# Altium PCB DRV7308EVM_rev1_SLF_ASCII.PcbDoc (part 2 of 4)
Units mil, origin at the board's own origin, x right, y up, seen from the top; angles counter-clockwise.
Board outline 6187 x 6000 mil, 4 copper layers (Top Layer, Ground, Power, Bottom Layer), stack 61.2 mil thick; 306 components, 128 nets, 676 pads, 1026 vias.
Unrouted connection lines stored in the file: 208.
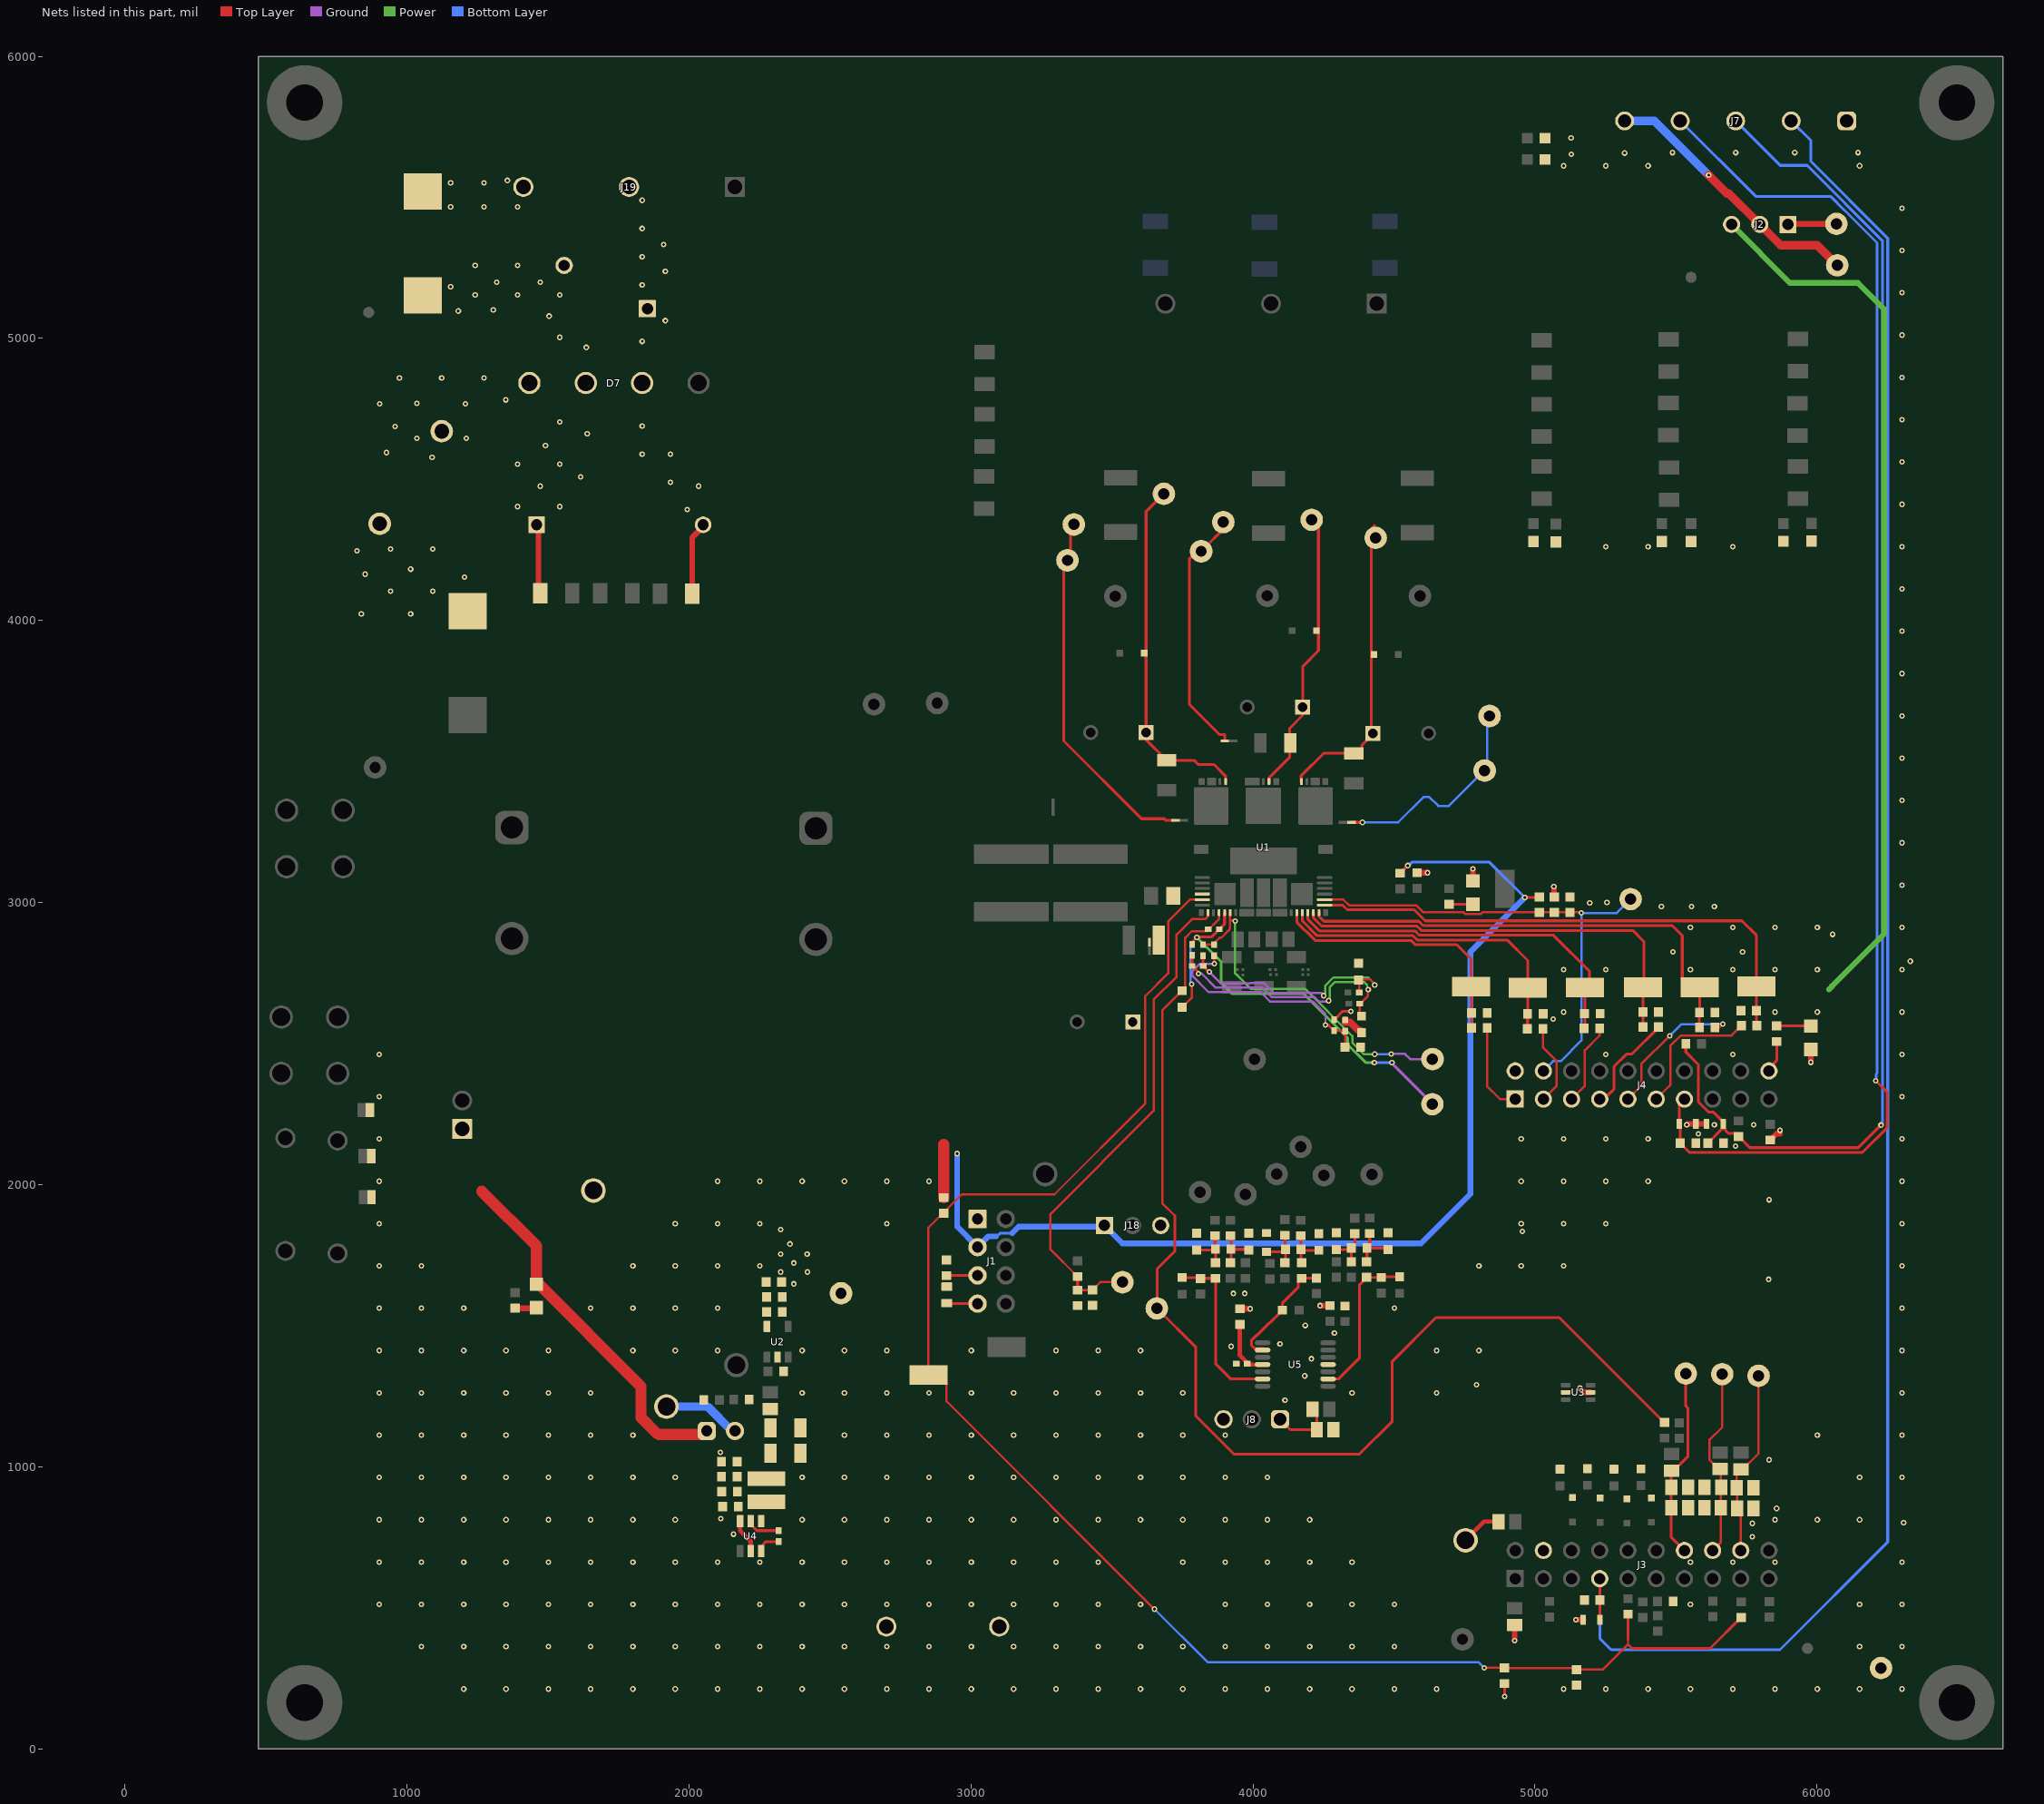
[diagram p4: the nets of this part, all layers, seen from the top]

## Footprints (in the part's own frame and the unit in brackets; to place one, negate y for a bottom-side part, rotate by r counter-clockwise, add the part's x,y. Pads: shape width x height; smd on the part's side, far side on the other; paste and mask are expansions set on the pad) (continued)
PW0014A_N [mm] "TSOP, 14-Leads, Body 5x4.4mm, Pitch 0.65mm, IPC Medium Density"
  oval 1.4x0.45 smd: 1(-2.95,1.95) 2(-2.95,1.3) 3(-2.95,0.65) 4(-2.95,0) 5(-2.95,-0.65) 6(-2.95,-1.3) 7(-2.95,-1.95) 8(2.95,-1.95) 9(2.95,-1.3) 10(2.95,-0.65) 11(2.95,0) 12(2.95,0.65) 13(2.95,1.3) 14(2.95,1.95)
  silkscreen extent -3.4,-2.55 1.85,2.55
REN0065A-MFG [mm]
  rrect22% 0.6x0.446 smd paste+0 mask+0: 1(-5.9,5.598) 23(-5.9,-5.598)
  rrect40% 0.6x0.25 smd paste+0 mask+0: 2(-5.9,5) 3(-5.9,4.5) 4(-5.9,4) 5(-5.9,3.5) 6(-5.9,3) 7(-5.9,2.5) 17(-5.9,-2.5) 18(-5.9,-3) 19(-5.9,-3.5) 20(-5.9,-4) 21(-5.9,-4.5) 22(-5.9,-5) 40(5.9,-3.916) 41(5.9,-3.416) 43(5.9,-0.5) 44(5.9,0) 48(5.9,3.416) 49(5.9,3.916)
  rrect40% 0.6x0.25 smd paste-1000 mask+0: 8(-5.9,2) 9(-5.9,1.5) 10(-5.9,1) 11(-5.9,0.5) 12(-5.9,0) 13(-5.9,-0.5) 14(-5.9,-1) 15(-5.9,-1.5) 16(-5.9,-2) 38(5.9,-4.916) 39(5.9,-4.416) 45(5.9,0.5) 46(5.9,1) 47(5.9,1.5) 50(5.9,4.416) 51(5.9,4.916)
  rrect40% 0.25x1.375 smd paste-1000 mask+0: 24(-5.225,-5.513) 25(-4.725,-5.513) 26(-4.225,-5.513) 27(-3.725,-5.513) 28(-3.225,-5.513) 29(-2.725,-5.513) 60(-2.725,5.513) 61(-3.225,5.513) 62(-3.725,5.513) 63(-4.225,5.513) 64(-4.725,5.513) 65(-5.225,5.513)
  rrect40% 0.25x0.45 smd paste+0 mask+0: 30(-0.45,-5.975) 31(0.05,-5.975) 58(0.05,5.975) 59(-0.45,5.975)
  rrect22% 0.5x0.455 smd paste+0 mask+0: 32(2.65,-5.973) 36(4.9,-5.973) 53(4.9,5.973) 57(2.65,5.973)
  rrect40% 0.25x0.455 smd paste+0 mask+0: 33(3.275,-5.973) 34(3.775,-5.973) 35(4.275,-5.973) 54(4.275,5.973) 55(3.775,5.973) 56(3.275,5.973)
  rrect18% 0.6x0.55 smd paste+0 mask+0: 37(5.9,-5.566) 42(5.9,-1.15) 52(5.9,5.566)
  rrect5% 1.975x1.94 smd paste-1000 mask+0: 66(-4.221,3.465) 70(-4.221,-3.465)
  rrect8% 2.601x1.25 smd paste-1000 mask+0: 67(-4.099,1.475) 69(-4.099,-1.475)
  rrect8% 2.601x1.2 smd paste-1000 mask+0: 68(-4.099,0)
  rrect4% 2.41x6 smd paste-1000 mask+0: 71(-1.233,0)
  rrect3% 3.278x3.175 smd paste-1000 mask+0: 72(3.711,0)
  rrect29% 0.7x1.35 smd paste-1000 mask+0: ""(-5.9,-1.5) ""(-5.9,0) ""(-5.9,1.5) ""(5.9,1)
  rrect24% 0.85x1.301 smd paste-1000 mask+0: ""(-0.2,5.6) ""(-0.2,-5.6)
  rrect6% 3.378x3.097 smd paste-1000 mask+0: ""(3.711,-4.702) ""(3.711,4.702)
  rrect29% 0.7x0.85 smd paste-1000 mask+0: ""(5.9,-4.666) ""(5.9,4.666)
  silkscreen extent -6.87,-6.43 6.43,6.43
Samtec_SSQ-110-03-x-D [mm] "Receptacle, 2.54mm, 10x2, TH"
  rect 1.55x1.55 hole 1.02: 1(-11.43,1.27)
  round 1.55 hole 1.02: 2(-11.43,-1.27) 3(-8.89,1.27) 4(-8.89,-1.27) 5(-6.35,1.27) 6(-6.35,-1.27) 7(-3.81,1.27) 8(-3.81,-1.27) 9(-1.27,1.27) 10(-1.27,-1.27) 11(1.27,1.27) 12(1.27,-1.27) 13(3.81,1.27) 14(3.81,-1.27) 15(6.35,1.27) 16(6.35,-1.27) 17(8.89,1.27) 18(8.89,-1.27) 19(11.43,1.27) 20(11.43,-1.27)
  silkscreen extent -12.95,-2.48 12.95,3
SNT-100-BK-G [mil] "Samtec STEP model"
  round 1 on Mech3: 0(0,0)
SOD-323 [mm] "NXP recommended land pattern"
  rect 0.6x0.6 smd paste-0.05: 1(-1.1,0) 2(1.1,0)
  silkscreen extent -2.06,-0.86 1.53,0.86
Testpoint_Keystone_Miniature [mil] "Miniature SMT test point"
  rect 135x70 smd: 1(0,0)
  silkscreen extent -78,-46 78,45
Thermistor_CL-40 [mil] "GE"
  round 80 hole 52: 1(-164,110) 2(164,-110)
  silkscreen extent -402,-118 402,118
TI_Stacked_Overlay_Small [mil]
TNPW0603 [mm] "Vishay"
  rect 0.5x0.9 smd: 1(-0.75,0) 2(0.75,0)
  silkscreen extent -0.2,-0.6 0.2,0.6
TSW-102-07-G-S [mm] "Samtec 100mil, 1x2, 230 mil above insulator"
  rrect50% 1.65x1.65 hole 1.016: 1(-1.27,0)
  round 1.65 hole 1.016: 2(1.27,0)
  silkscreen extent -3.17,-1.27 2.54,1.27
TSW-104-07-G-D [mm] "Samtec 100mil, 2x4, 230 mil above insulator"
  rrect6% 1.65x1.65 hole 1.016: 1(-3.81,-1.27)
  round 1.65 hole 1.016: 2(-3.81,1.27) 3(-1.27,-1.27) 4(-1.27,1.27) 5(1.27,-1.27) 6(1.27,1.27) 7(3.81,-1.27) 8(3.81,1.27)
  silkscreen extent -6.1,-2.54 5.08,2.54
WCAP-CSGP_0603_L1.6W0.8H0.8_Reflow [mm] "Ceramic Capacitors, body 1.6x0.8mm"
  rect 0.8x0.8 smd: 1(-0.75,0) 2(0.75,0)
WCAP-CSGP_0603_L1.6W0.8H0.8_Wave [mm] "Ceramic Capacitors, 0603, body 1.6x0.8mm"
  rect 0.7x0.8 smd: 1(-0.85,0) 2(0.85,0)
WE-MAIA_3015 [mm] "SMD, 2-Leads, Body 3x3mm"
  rect 1.3x3.4 smd: 1(-1.05,0) 2(1.05,0)
  silkscreen extent -0.1,-1.6 0.1,1.6
WEEE_Minimum [mil] "WEEElie bin"
  silkscreen extent 22,-71 54,74
WURTH_61300311121 [mm] "Header, 2.54mm, 3x1, TH"
  rrect50% 1.65x1.65 hole 1.15: 1(-2.54,0)
  round 1.65 hole 1.15: 2(0,0) 3(2.54,0)

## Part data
C1 C3 C5: library part CMP-0008509-2, "CAP, CERM, 1 uF, 25 V, +/- 10%, X7R, 1206"
C2: library part CMP-0006343-2, "CAP, CERM, 0.1 uF, 10 V, +/- 10%, X7R, 0402"
C4 C47 C48 C49: library part CMP-0007796-2, "CAP, CERM, 470 pF, 50 V, +/- 10%, X7R, 0805"
C6 C8: library part CMP-0097628-1, "2225 0.1 uF 1 kV ±10 % Tolerance X7R SMT Multilayer Ceramic Chip Capacitor"
C7 C35 C52: library part CMP-0006837-2, "CAP, CERM, 0.1 uF, 50 V, +/- 10%, X7R, 0603"
C9: library part CMP-0007567-1, "CAP, CERM, 0.1 uF, 25 V, +/- 10%, X7R, 0805"
C10: library part CMP-0009224-2, "CAP, CERM, 22 uF, 25 V, +/- 10%, X7R, 1210"
C11: library part CMP-0860561-1, "CAP, CERM, 0.01 µF, 25 V,+/- 10%, X7R, 0402"
C12 C16 C17 C24 C36 C37 C40 C41 C43 C44 C46 C50: library part CMP-0104643-1, "WCAP-CSGP Multilayer Ceramic Chip Capacitor, General Purpose, size 0603, X7R, 100pF, 10VDC"
C13 C14 C15 C34: library part CMP-0086483-1, "0.047µF ±10% 25V Ceramic Capacitor X7R 0603 (1608 Metric)"
C18 C19 C20 C21 C22 C23: library part CMP-0064933-2, "CAP, CERM, 1000 pF, 50 V,+/- 10%, X7R, 0603"
C25 C26 C27: library part CMP-0006826-2, "CAP, CERM, 1000 pF, 16 V, +/- 10%, X7R, 0603"
C28 C55: library part CMP-0007505-3, "CAP, CERM, 1 uF, 10 V, +/- 10%, X7R, AEC-Q200 Grade 1, 0603"
C29 C30 C31: library part CMP-0076705-1, "CAP, CERM, 1 µF, 25 V,+/- 10%, X7R, AEC-Q200 Grade 1, 0603"
C32 C54: library part CMP-0080740-1, "CAP, CERM, 10 µF, 25 V,+/- 10%, X7R, 1206"
C33: library part CMP-0007119-4, "CAP, CERM, 0.1 uF, 16 V, +/- 10%, X7R, 0603"
C38: library part CMP-0006263-2, "CAP, CERM, 2.2 uF, 10 V, +/- 10%, X5R, 0402"
C39 C42 C45: library part CMP-0006826-4, "CAP, CERM, 1000 pF, 16 V, +/- 10%, X7R, 0603"
C53: library part CMP-0006726-4, "CAP, CERM, 0.01 uF, 100 V, +/- 5%, X7R, 0603"
C56: library part CMP-0012410-1, "CAP, Film, 0.33 uF, 630 V, +/- 20%, TH"
C57 C58: library part CMP-0085509-1, "CAP, AL, 150 µF, 450 V, +/- 20%, 1.216 ohm, TH"
C59 C60 C61: library part CMP-0010527-1, "CAP, AL, 220 uF, 25 V, +/- 20%, 0.1 ohm, TH"
C62 C63 C64: library part CMP-0009436-1, "CAP, CERM, 1000 pF, 2000 V, +/- 10%, X7R, 1808"
C67: library part CMP-0010362-1, "CAP, AL, 1000 uF, 25 V, +/- 20%, TH"
D2: library part CMP-0002829-1, "LED, Red, SMD"
D3: library part CMP-0002888-1, "LED, Green, SMD"
D4: library part CMP-0002890-1, "LED, Orange, SMD"
D7: library part CMP-0029245-3, "Diode, Switching-Bridge, 600 V, 6 A, TH"
D9 D10 D11 D12: library part CMP-0084035-2, "Diode, Schottky, 7 V, 0.01 A, SOD-323"
D14 D15 D16: library part CMP-0005835-4, "Diode, Zener, 18 V, 200 mW, SOD-323"
F1 F2: library part CMP-0003468-2, "Fuse, 3 A, 250VAC/VDC, SMD"
FID1 FID2 FID3: library part CMP-0077181-1, "Fiducial mark.  There is nothing to buy or mount."
H9 H10 H11 H12: library part CMP-0003640-1, "Standoff, Hex,25mm Length, M3, Aluminum"
H13 H14 H15 H16: library part CMP-0003646-1, "MACHINE SCREW PAN PHILLIPS M3 5mm"
J1: library part CMP-0075408-2, "Header, 100mil, 4x2, Gold, TH"
J2 J18: library part CMP-0065026-1, "Header, 2.54mm, 3x1, Tin, TH"
J3 J4: library part CMP-0075613-1, "Receptacle, 2.54mm, 10x2, Gold, TH"
J5: library part CMP-0055418-2, "Banana Jack Insul Nylon Red, R/A, TH"
J6 J19: library part CMP-0055528-1, "Terminal Block, 9.52mm, 3x1, R/A, TH"
J7: library part CMP-0055532-1, "Terminal Block, 5mm, 5x1, R/A, TH"
J8: library part CMP-0054796-2, "Header, 2.54 mm, 3x1, Gold, TH"
J9: library part CMP-0075076-1, "Terminal Block, 2.54mm, 2x1, Brass, TH"
J10: library part CMP-0055417-2, "Banana Jack Insul Nylon Black, R/A, TH"
J17: library part CMP-0075405-3, "Header, 100mil, 2x1, Gold, TH"
L1: library part CMP-0064361-1, "Inductor, Shielded, Powdered Iron, 4.7 uH, 1.5 A, 0.162 ohm, AEC-Q200 Grade 1, SMD"
L2 L3 L4: library part CMP-0003168-1, "Ferrite Bead, 120 ohm @ 100 MHz, 3 A, 1812"
LOGO LOGO5 LOGO7: library part CMP-0074837-1, "IEC 61010-1 Hot Surface Warning"
Logo1: library part CMP-0074844-1
Logo2: library part CMP-0074838-1, "Texas Instrument Corporate Signature"
Logo3: library part CMP-0074847-1, "FCC_disclaimer"
Logo4: library part CMP-0074769-1
LOGO6 LOGO8: library part CMP-0074835-1, "IEC 61010-1 High Voltage Warning"
MH5 MH6 MH7 MH8: library part CMP-0078423-2, "PCB Mounting Hole"
NT1 NT2 NT14: library part CMP-0078142-1, "Single point connection between nets."
NT3 NT4 NT5 NT6 NT7 NT8 NT9 NT10 NT11 NT12 NT13: library part CMP-0078142-4, "Single point connection between nets."
R1: library part CMP-0022073-1, "RES, 162 k, 1%, 0.1 W, 0603"
R2 R48 R49 R50 R51 R54 R78 R79 R135 R137 R138 R139: library part CMP-0025874-4, "RES, 0, 5%, 0.1 W, AEC-Q200 Grade 0, 0603"
R3 R6 R37: library part CMP-0017262-1, "RES, 0.03, 1%, 0.5 W, 1206"
R4: library part CMP-0024951-1, "RES, 22.1 k, 0.5%, 0.1 W, 0603"
R5 R21: library part CMP-0020616-1, "RES, 0, 5%, 0.125 W, 0805"
R7 R13 R36: library part CMP-0020616-3, "RES, 0, 5%, 0.125 W, AEC-Q200 Grade 0, 0805"
R8 R45 R128: library part CMP-0026162-2, "RES, 20.0 k, 1%, 0.063 W, AEC-Q200 Grade 0, 0402"
R9 R11: library part CMP-0025964-3, "RES, 10.2, 1%, 0.063 W, AEC-Q200 Grade 0, 0402"
R10 R12 R129: library part CMP-0026676-1, "RES, 2.00 k, 1%, 0.1 W, AEC-Q200 Grade 0, 0402"
R14 R70 R71 R72: library part CMP-0082535-1, "RES, 330, 1%, 0.125 W, 0805"
R15 R17: library part CMP-0078582-1, "RES, 330, 0.1%, 0.1 W, AEC-Q200 Grade 0, 0603"
R16: library part CMP-0024300-2, "RES, 4.70 k, 0.1%, 0.1 W, 0603"
R18 R19 R20 R75 R76 R77 R120: library part CMP-0022736-4, "RES, 100, 1%, 0.1 W, 0603"
R22 R121 R122: library part CMP-0018205-2, "RES, 330 k, 1%, 0.25 W, 1206"
R29 R30 R31: library part CMP-0025686-1, "RES, 10.0 k, 0.1%, 0.1 W, AEC-Q200 Grade 1, 0603"
R34 R41 R117 R123 R124 R125 R126 R127: library part CMP-0025830-1, "RES, 5.1 k, 5%, 0.1 W, 0603"
R43: library part CMP-0025701-4, "RES, 10 k, 5%, 0.1 W, AEC-Q200 Grade 0, 0603"
R44: library part CMP-0095619-1, "RES Thick Film, 68kO, 1%, 0.1W, 100ppm/°C, 0603"
R46 R57 R58 R63 R64 R69 R118: library part CMP-0022447-4, "RES, 49.9 k, 1%, 0.1 W, AEC-Q200 Grade 0, 0603"
R47: library part CMP-0025697-4, "RES, 0, 5%, 0.1 W, AEC-Q200 Grade 0, 0603"
R52 R55 R59 R61 R65 R67: library part CMP-0022005-4, "RES, 10.2, 1%, 0.1 W, AEC-Q200 Grade 0, 0603"
R53 R56 R60 R62 R66 R68: library part CMP-0022458-4, "RES, 4.99 k, 1%, 0.1 W, AEC-Q200 Grade 0, 0603"
R73 R74: library part CMP-0021990-4, "RES, 100 k, 1%, 0.1 W, AEC-Q200 Grade 0, 0603"
R91 R92 R93 R94 R98 R110 R111 R112 R113 R116 R130 R134: library part CMP-0018207-2, "RES, 332 k, 1%, 0.25 W, 1206"
R99 R100 R101 R102 R103 R104 R105 R106: library part CMP-0023308-5, "RES, 8.20 k, 1%, 0.1 W, 0603"
R107 R108 R109: library part CMP-0021042-1, "RES, 20.0 k, 1%, 0.125 W, 0805"
R119: library part CMP-0022280-2, "RES, 2.67 k, 1%, 0.1 W, 0603"
RT1: library part CMP-0002561-2, "Thermistor NTC, 5 ohm, 25%, Disc, 220x770 mil"
RV1: library part CMP-0086467-2, "Var MOV 350VAC/460VDC 3500A 560V Radial Bulk"
SH-J1 SH-J2 SH-J3 SH-J4 SH-J5: library part CMP-0003623-3, "Shunt, 100mil, Gold plated, Black"
TP1 TP2 TP3: library part CMP-0055137-1, "Test Point, Miniature, Red, TH"
TP4 TP5 TP6 TP7 TP9 TP10 TP29 TP32 TP34 TP35 TP40 TP41: library part CMP-0055137-2, "Test Point, Miniature, Red, TH"
TP8 TP18 TP20 TP21 TP22 TP23 TP24 TP43 TP45: library part CMP-0055152-1, "Test Point, Miniature, SMT"
TP11 TP12 TP13: library part CMP-0075110-1, "1mm Uninsulated Shorting Plug, 10.16mm spacing, TH"
TP14 TP26 TP31 TP36 TP37 TP38 TP39 TP44 TP46 TP47 TP48 TP49 TP52 TP53 TP54 TP55 TP56 TP57: library part CMP-0055139-2, "Test Point, Miniature, White, TH"
TP16 TP17: library part CMP-0055138-1, "Test Point, Miniature, Black, TH"
TP19 TP30 TP33 TP42 TP50: library part CMP-0055146-2, "Test Point, Compact, Yellow, TH"
U1: library part CMP-0098388-1, "Three-Phase, 650-V Integrated GaN FET Motor Driver, VQFN65"
U2: library part CMP-0065093-2, "Low-Dropout Regulator, DBV0005A (SOT-23-5)"
U3: library part CMP-0043118-3, "4-Channel ESD Solution for High-Speed Differential Interface, DCK0006A (SOT-SC70-6)"
U4: library part CMP-0094075-1, "SIMPLE SWITCHER 4.5-V to 36-V, 2-A Buck Converter in SOT-23-6 Package"
U5: library part CMP-0082283-1, "4 channel, 10-MHz, Low-Noise, RRIO, CMOS Operational Amplifier for Cost-Sensitive Systems, PW0014A (TSSOP-14)"
ZZ1: library part CMP-0003616-3
ZZ2: library part CMP-0077236-1
ZZ3: library part CMP-0077237-1
ZZ4: library part CMP-0077238-1

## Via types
v1: diameter 20, hole 10, Top Layer to Bottom Layer, tented both sides, 933 vias
v2: diameter 19.68, hole 7.87, Top Layer to Bottom Layer, tented both sides, 57 vias
v3: diameter 39.37, hole 19.68, Top Layer to Bottom Layer, tented both sides, 24 vias
v4: diameter 20, hole 10, Top Layer to Bottom Layer, tented bottom, 12 vias

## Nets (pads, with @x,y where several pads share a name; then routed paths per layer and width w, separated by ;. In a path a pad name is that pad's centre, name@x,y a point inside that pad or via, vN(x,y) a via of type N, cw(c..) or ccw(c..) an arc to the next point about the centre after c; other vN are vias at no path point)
3V3: D2.1 D4.1 J2.3 J18.3 R8.2 R13.1 R29.2 R30.2 R31.2 R41.2 R47.2 R51.1 R54.2 R73.2 R117.1 R125.1 TP26.1 U3.5 | length 3762.8
  Top Layer w10: R8.2@4288,2584.69 4317.31,2614 v1(4347.27,2614) ; R117.1@4891.82,231 4891.82,186 v1(4892.82,185)
  Top Layer w20: R47.2@3953.26,1559.7 v1(3989.7,1559.7) ; v1(4237.82,1570.7) R73.2@4273.26,1570.7 ; R41.2@4582,3105.56 v1(4618.56,3105.56) ; D2.1@4780,3076.76 v1(4780,3119) ; v1(4927.82,383) R13.1@4927.82,439.07 ; v1(5066.9,3056.78) 5068,3055.69 R125.1@5068,3019.56 ; v1(5144.82,457) R31.2@5171.29,457 ; v1(5159.09,1278.38) 5173.37,1264.1 5196.66,1264.1 U3.5@5197.38,1263.38 ; v1(5538.18,2211.89) 5541.29,2215 R30.2@5608.29,2215 ; R51.1@5834.82,2158.44 5857.19,2180.81 5868.55,2180.81 v1(5868.55,2192.17) ; v1(5978.28,2433.42) D4.1@5978.28,2479.08
  Power w20: J2.3@5697,5404 5904,5197 6145.13,5197 6238,5104.13 6238,2889 6053,2704 6053,2702 6043,2692
  other v1: 2372,1648 2325,1690 2420,1690 2372,1722 2325,1754 2419,1754 2358,1789.53 2325,1840
+5V: R36.2 TP30.1 | length 144.8
  Top Layer w15: TP30.1@4753.82,739 4819.82,805 R36.2@4871.29,805
AMPIN+: R10.2 R45.1 TP37.1 U1.6 | length 1226.3
  Top Layer w8: R10.2@3824,2850.69 R45.1@3860,2850.69 ; R45.1@3863,2853.69 R45.1@3860,2850.69 ; U1.6@3918.96,2964.09 3918.96,2937 ; v1(3936.5,2934.5) 3934,2937 3918.96,2937 ; R45.1@3860,2850.69 3860,2853.7 3881.3,2875 3887.89,2875 3912.82,2899.92 3912.82,2901.12 3918.96,2907.26 3918.96,2937
  Ground w8: v1(4489.99,2463.16) 4539.17,2463.16 4557.32,2445.01 TP37.1@4636.51,2445.01
  Power w8: v1(3936.5,2934.5) 3936.5,2749.15 3991.65,2694 4184.84,2694 4352.46,2526.38 4352.46,2503.3 4393.76,2462 v1(4431.61,2462)
  Bottom Layer w8: v1(4431.61,2462) 4484.45,2462 4485.6,2463.16 v1(4489.99,2463.16)
AMPIN-: C16.1 R12.2 R128.1 TP38.1 U1.5 | length 1595.3
  Top Layer w8: C16.1@3749,2628.47 3782.84,2662.31 v1(3782.84,2710.29)
  Top Layer w10: R12.2@3784,2851.69 3784,2859 v1(3801,2876) 3802.5,2877.5 3852.43,2877.5 3872.94,2898 3873.68,2898 3899.28,2923.59 U1.5@3899.28,2964.09
  Ground w10: v1(4492.77,2432.8) 4492.77,2430.52 4636,2287.29 TP38.1@4636,2285
  Power w10: v1(3801,2876) 3801.76,2876 3886.54,2791.22 3886.54,2716.18 3925.18,2677.54 4178.02,2677.54 4336,2519.56 4336,2496.48 4399.68,2432.8 v1(4430.19,2432.8)
  Bottom Layer w8: v1@3778.66,2715.64 3778.66,2853.66 v1(3801,2876)
  Bottom Layer w10: v1(4430.19,2432.8) v1(4492.77,2432.8)
AMPOUT: C16.2 R78.2 R128.2 TP39.1 U1.4 | length 4197.4
  Top Layer w8: 3722.56,1889.44 3678.57,1933.43 3678.57,2617.1 C16.2@3749,2687.53 3759.87,2698.4 3759.87,2875 3782.87,2898 3836.48,2898 3879.59,2941.12 U1.4@3879.59,2964.09
  Top Layer w10: 3722.56,1889.44 3722.56,1763.39 3660,1700.83 3660,1560.52 3797.26,1423.27 3797.26,1179.28 3932.54,1044 4377.04,1044 4494,1160.96 4494,1373.61 4648.97,1528.57 5085.82,1528.57 5457.83,1156.56 R78.2@5458.82,1156.56
BK_OUT: C32.1 C54.1 L1.2 R1.2 R7.1
BRAKE: J4.4 R124.2 R125.2 R126.2 TP44.1 U1.25 | length 1760.5
  Top Layer w8: U1.25@4254.12,3010.35 4320.6,3010.35 4340.67,2990.28 4578.47,2990.28 4603.87,2964.88 4746.4,2964.88 4751.82,2959.46 4808.18,2959.46 4813.6,2964.88 R126.2@5124,2964.88 v1@5164.42,2964.88
  Bottom Layer w8: J4.4@5029.5,2403.32 J4.4@5029.82,2403 5064.48,2437.66 5091.25,2437.66 5164.42,2510.82 v1(5164.42,2963) 5289.98,2963 TP44.1@5339.09,3012.11
ENABLE: R2.1 R34.2 R49.1 R117.2 R123.2 TP43.1 U1.64 | length 5851.6
  Top Layer w8: TP43.1@2848.59,1325 2848.59,1846.59 2967.01,1965.01 3296.01,1965.01 3617.99,2286.99 3617.99,2667.99 3699,2749 3699,2932.94 3776.41,3010.35 U1.64@3820.02,3010.35 ; TP43.1@2850,1325 2882.5,1325 2913.5,1294 2913.5,1231.5 3648,497 3649,497 v1(3651,495) ; v1(4819.7,286.69) 4891.25,286.69 R117.2@4891.82,286.12 5141.26,286.12 R123.2@5146.82,280.56 5240.5,280.56 5329.93,369.99 5329.93,386
  Top Layer w10: 5329.93,369.99 5344.37,355.55 5620.93,355.55 R49.1@5730.82,465.44 ; 5329.93,386 R2.1@5329.93,477
  Bottom Layer w8: v1(3651,495) 3840,306 4800.39,306 v1(4819.7,286.69)
GND: C4.2 C7.2 C12.1 C13.1 C14.1 C15.1 C18.2 C19.2 C20.2 C21.2 C22.2 C23.2 C25.2 C26.2 C27.2 C28.2 C29.2 C30.2 C31.2 C32.2 C33.2 C34.1 C35.2 C36.2 C37.1 C38.1 C40.2 C41.1 C43.2 C44.1 C46.2 C47.2 C48.2 C49.2 C52.1 C53.2 C54.2 C55.2 D9.2 D10.2 D11.2 D12.2 J1.1 J3.4 J4.2 J7.1 J8.3 NT1.1 NT2.1 NT14.1 R4.1 R43.1 R44.1 R74.1 R99.1 R100.1 R101.1 R102.1 R103.1 R104.1 R105.1 R106.1 R107.1 R108.1 R109.1 R119.1 R123.1 R126.1 R129.1 TP11.1 TP11.2 TP16.1 U2.2 U3.2 U4.1 U5.11 | length 77.3
  Top Layer w10: v1(5064.29,2586.56) v1@5066.99,2586.56
  Top Layer w25: R129.1@4327,2583.69 4327,2575.63 4344.92,2575.63 4374.1,2546.44 C36.2@4381,2546.44
  Top Layer w30: J7.1@6105.44,5771 J7.1@6105.76,5770.68
  other v1: 1201.27,211.79 1351.27,211.79 1501.27,211.79 1651.27,211.79 1801.27,211.79 1951.27,211.79 2101.27,211.79 2251.27,211.79 2401.27,211.79 2551.27,211.79 2701.27,211.79 2851.27,211.79 3001.27,211.79 3151.27,211.79 3301.27,211.79 3451.27,211.79 3601.27,211.79 3751.27,211.79 3901.27,211.79 4051.27,211.79 4201.27,211.79 4351.27,211.79 4501.27,211.79 4651.27,211.79 5101.27,211.79 5251.27,211.79 5401.27,211.79 5551.27,211.79 5701.27,211.79 5851.27,211.79 6001.27,211.79 6151.27,211.79 6301.27,211.79 1051.27,361.79 1201.27,361.79 1351.27,361.79 1501.27,361.79 1651.27,361.79 1801.27,361.79 1951.27,361.79 2101.27,361.79 2251.27,361.79 2401.27,361.79 2551.27,361.79 2701.27,361.79 2851.27,361.79 3001.27,361.79 3151.27,361.79 3301.27,361.79 3451.27,361.79 3601.27,361.79 3751.27,361.79 3901.27,361.79 4051.27,361.79 4201.27,361.79 4351.27,361.79 4501.27,361.79 6151.27,361.79 6301.27,361.79 901.27,511.79 1051.27,511.79 1201.27,511.79 1351.27,511.79 1501.27,511.79 1651.27,511.79 1801.27,511.79 1951.27,511.79 2101.27,511.79 2251.27,511.79 2401.27,511.79 2551.27,511.79 2701.27,511.79 2851.27,511.79 3001.27,511.79 3151.27,511.79 3301.27,511.79 3451.27,511.79 3601.27,511.79 3901.27,511.79 4051.27,511.79 4201.27,511.79 4351.27,511.79 4501.27,511.79 5551.27,511.79 6151.27,511.79 6301.27,511.79 901.27,661.79 1051.27,661.79 1201.27,661.79 1351.27,661.79 1501.27,661.79 1651.27,661.79 1801.27,661.79 1951.27,661.79 2101.27,661.79 2251.27,661.79 2401.27,661.79 2551.27,661.79 2701.27,661.79 2851.27,661.79 3001.27,661.79 3151.27,661.79 3301.27,661.79 3451.27,661.79 3751.27,661.79 3901.27,661.79 4051.27,661.79 4201.27,661.79 4351.27,661.79 5551.27,661.79 5701.27,661.79 5851.27,661.79 6301.27,661.79 5770.82,751 2158,760.56 5770.82,799 6307,801 901.27,811.79 1051.27,811.79 1201.27,811.79 1351.27,811.79 1501.27,811.79 1651.27,811.79 1801.27,811.79 1951.27,811.79 2401.27,811.79 2551.27,811.79 2701.27,811.79 2851.27,811.79 3001.27,811.79 3151.27,811.79 3301.27,811.79 3451.27,811.79 3601.27,811.79 3751.27,811.79 3901.27,811.79 4051.27,811.79 4201.27,811.79 5851.27,811.79 6001.27,811.79 6151.27,811.79 2113,816 5856.82,852 901.27,961.79 1051.27,961.79 1201.27,961.79 1351.27,961.79 1501.27,961.79 1651.27,961.79 1801.27,961.79 1951.27,961.79 2401.27,961.79 2551.27,961.79 2701.27,961.79 2851.27,961.79 3001.27,961.79 3151.27,961.79 3301.27,961.79 3451.27,961.79 3601.27,961.79 3751.27,961.79 3901.27,961.79 4051.27,961.79 6151.27,961.79 6301.27,961.79 5829.93,1024 2111,1051 901.27,1111.79 1051.27,1111.79 1201.27,1111.79 1351.27,1111.79 1501.27,1111.79 1651.27,1111.79 1801.27,1111.79 2551.27,1111.79 2701.27,1111.79 2851.27,1111.79 3001.27,1111.79 3151.27,1111.79 3301.27,1111.79 3451.27,1111.79 3601.27,1111.79 3751.27,1111.79 3901.27,1111.79 6001.27,1111.79 6301.27,1111.79 4113.28,1235.27 901.27,1261.79 1051.27,1261.79 1201.27,1261.79 1351.27,1261.79 1501.27,1261.79 1651.27,1261.79 2401.27,1261.79 2551.27,1261.79 2701.27,1261.79 2851.27,1261.79 3001.27,1261.79 3151.27,1261.79 3301.27,1261.79 3451.27,1261.79 3601.27,1261.79 3751.27,1261.79 4351.27,1261.79 4651.27,1261.79 6301.27,1261.79 4792.67,1290.26 4183.57,1321.76 4207.26,1382.5 901.27,1411.79 1051.27,1411.79 1201.27,1411.79 1351.27,1411.79 1501.27,1411.79 1801.27,1411.79 1951.27,1411.79 2101.27,1411.79 2401.27,1411.79 2551.27,1411.79 2701.27,1411.79 3001.27,1411.79 3301.27,1411.79 3451.27,1411.79 3601.27,1411.79 4651.27,1411.79 4801.27,1411.79 6301.27,1411.79 3922.26,1426.14 4095.7,1435.42 4288.7,1473.77 4185.52,1500.52 901.27,1561.79 1051.27,1561.79 1201.27,1561.79 1651.27,1561.79 1801.27,1561.79 1951.27,1561.79 2101.27,1561.79 4501.27,1561.79 6301.27,1561.79 3930.54,1614.14 3970.26,1614.14 5828.82,1664 901.27,1711.79 1051.27,1711.79 1801.27,1711.79 1951.27,1711.79 2101.27,1711.79 2251.27,1711.79 4801.27,1711.79 4951.27,1711.79 5101.27,1711.79 6301.27,1711.79 4955.5,1834 901.27,1861.79 1951.27,1861.79 2101.27,1861.79 2251.27,1861.79 2701.27,1861.79 4951.27,1861.79 5101.27,1861.79 5251.27,1861.79 6301.27,1861.79 5829.97,1946 901.27,2011.79 2101.27,2011.79 2251.27,2011.79 2401.27,2011.79 2551.27,2011.79 2701.27,2011.79 2851.27,2011.79 4951.27,2011.79 5101.27,2011.79 5251.27,2011.79 5401.27,2011.79 6301.27,2011.79 5711,2136 901.27,2161.79 4951.27,2161.79 5101.27,2161.79 5251.27,2161.79 5401.27,2161.79 6301.27,2161.79 5579,2180 5636.19,2211.89 5775.45,2211.89 901.27,2311.79 6301.27,2311.79 901.27,2461.79 5251.27,2461.79 5701.27,2461.79 6301.27,2461.79 5101.27,2611.79 5851.27,2611.79 6001.27,2611.79 6301.27,2611.79 5101.27,2761.79 5251.27,2761.79 5551.27,2761.79 5701.27,2761.79 5851.27,2761.79 6001.27,2761.79 6301.27,2761.79 6331.1,2792 5489.02,2824.53 5736.02,2824.53 6055.09,2887.12 5551.27,2911.79 5701.27,2911.79 5851.27,2911.79 6001.27,2911.79 6301.27,2911.79 5448,2986 5555.15,2986 5636.19,2986 5194,2999 5255,3000 6301.27,3061.79 6301.27,3211.79 6301.27,3361.79 6301.27,3511.79 6301.27,3661.79 6301.27,3811.79 6301.27,3961.79 6301.27,4111.79 5251.27,4261.79 5401.27,4261.79 5701.27,4261.79 6301.27,4261.79 6301.27,4411.79 6301.27,4561.79 6301.27,4711.79 6301.27,4861.79 6301.27,5011.79 6301.27,5161.79 6301.27,5311.79 6301.27,5461.79 5101.27,5611.79 5251.27,5611.79 5401.27,5611.79 6151.27,5611.79 5129,5653 5318.04,5657.08 5487.46,5658.76 5711.74,5658.76 5921,5658.76 6145.13,5658.76 5128,5711
GVDD: C9.2 C10.2 C67.1 D3.1 J1.3 J9.1 J17.1 J18.1 NT13.2 R34.1 R124.1 R127.1 TP42.1 U1.63 | length 5414.4
  Top Layer w10: R127.1@4522,3103.94 v1(4549.06,3131) ; v1(4964.03,3017.96) 5013.4,3017.96 R124.1@5015,3019.56
  Top Layer w40: 1265,1976 1459,1782 D3.1@1459,1655 ; D3.1@1459,1646.68 D3.1@1459,1655 ; 1885,1119 1829.66,1174.34 1829.66,1284.34 D3.1@1459,1655 ; 1893,1114.44 2051,1114.44 J17.1@2063,1126.44 ; R34.1@2904,1953.56 2904,2142
  Bottom Layer w10: 3090.5,1814.5 3104,1828 3146.03,1828 ; v1(4549.06,3131) 4551.77,3131 4563.77,3143 4838.99,3143 v1(4964.03,3017.96)
  Bottom Layer w20: v1(2951,2110) 2951,1850.23 J1.3@3023.23,1778 3061.52,1816.29 3088.71,1816.29 ; 3146.03,1828 3169.03,1851 3477,1851 3536.61,1791.39 4595.39,1791.39 4699,1895 4771,1967 4771,2824.93 v1(4964.03,3017.96)
HALL_PWR: J2.2 J7.5 TP53.1 | length 966
  Top Layer w30: v1(5615.68,5578.78) 5680.46,5514 5687,5514 J2.2@5797,5404 5871,5330 6001,5330 TP53.1@6072,5259
  Bottom Layer w30: J7.5@5318.04,5771 5423.46,5771 v1(5615.68,5578.78)
HALLA: C25.1 J4.13 J7.4 R29.1 | length 4983.2
  Top Layer w10: J4.13@5529.82,2303 5511.29,2284.47 R29.1@5511.29,2215 5515.26,2211.03 C25.1@5515.26,2147 5515.26,2146.02 5547.58,2113.69 6160.81,2113.69 6249,2201.89 6249,2326.87 v1(6208,2367.87)
  Bottom Layer w10: J7.4@5514.89,5771 5782.39,5503.5 6047.87,5503.5 6096.37,5455 6097,5455 6213,5339 6213,2395 6209.91,2391.91 6209.91,2369.78 v1(6208,2367.87)
HALLB: C26.1 J7.3 R30.1 R138.1 R139.2 | length 4884.2
  Top Layer w10: R139.2@5535.14,2498.69 5535.14,2469.83 5579.46,2425.51 5579.46,2293.24 5616.14,2256.55 5633.67,2256.55 5667.35,2222.87 R30.1@5667.35,2215 ; C26.1@5613.26,2147 5667.35,2201.09 5687.22,2181.21 5710.89,2181.21 R138.1@5721.64,2170.47 5722.63,2170.47 5762.4,2130.69 6146.69,2130.69 v1(6227,2211)
  Bottom Layer w10: J7.3@5711.74,5767.94 J7.3@5711.74,5771 5869.22,5613.52 5965.35,5613.52 6232,5346.87 6232,2216 v1(6227,2211)
HALLC: C27.1 J3.7 J7.2 R31.1 | length 6734.2
  Top Layer w10: J3.7@5229.82,603 5229.82,527.56 C27.1@5229.93,527.45 ; R31.1@5229.93,457 C27.1@5229.93,527.45 ; C27.1@5230.38,527 C27.1@5229.93,527.45
  Bottom Layer w10: J3.7@5229.82,603 5229.82,391.06 5269.88,351 5868.63,351 6251,733.37 6251,5354.74 5978.78,5626.96 5978.78,5700.81 J7.2@5908.59,5771
ILIMIT: C35.1 R118.1 R119.2 TP36.1 U1.2 | length 1808.8
  Top Layer w8: R119.2@3378,1626 3377.56,1625.56 3430,1625.56 C35.1@3431,1626.56 3458.44,1654 TP36.1@3537,1654 ; R118.1@3378,1673.88 3282,1769.88 3282,1895.35 3648,2261.35 3648,2655.57 3729,2736.57 3729,2886.56 3783.73,2941.28 3831.28,2941.28 3840.22,2950.22 U1.2@3840.22,2964.09
  Top Layer w10: R119.2@3378,1626 R118.1@3378,1673.88
INHA: J4.1 R18.1 | length 327.4
  Top Layer w8: R18.1@4830.15,2555.59 4830.15,2348.58 4875.72,2303 J4.1@4929.82,2303
  Bottom Layer w8: J4.1@4931.12,2301.69 J4.1@4932.43,2303
INHA_DRV: C18.1 R18.2 TP8.1 U1.18 | length 951.1
  Top Layer w10: U1.18@4155.18,2964.09 4155.18,2930.78 4220.46,2865.5 4560.42,2865.5 4575.78,2850.13 4723.75,2850.13 4773.59,2800.29 TP8.1@4773.59,2701.59 4775.03,2700.15 C18.1@4775.03,2608.59 R18.2@4775.03,2555.59
INHB: J4.5 R20.1 | length 294.3
  Top Layer w8: J4.5@5129.82,2303 5177.02,2350.2 5177.02,2475.87 5229.15,2528 R20.1@5229.15,2553.59
  Bottom Layer w8: J4.5@5129.82,2303 J4.5@5132.43,2303
INHB_DRV: C20.1 R20.2 TP18.1 U1.20 | length 1308.9
  Top Layer w10: U1.20@4194.55,2964.09 4194.55,2940.45 4235.5,2899.5 4574.5,2899.5 4589.87,2884.13 5065.64,2884.13 5192.59,2757.19 5192.59,2713.59 TP18.1@5177.59,2698.59 5177.59,2557.15 R20.2@5174.03,2553.59
INHC: J4.9 R76.1 | length 528.1
  Top Layer w8: J4.9@5329.82,2303 5377.02,2350.2 5377.02,2427.37 v1@5477.3,2527.66 ; R76.1@5638.15,2555.6 R76.1@5638.15,2556.59 5654.21,2556.59 v1(5666.49,2568.87)
  Bottom Layer w8: J4.9@5331.12,2301.69 J4.9@5332.43,2303 ; v1(5477.68,2527.28) 5519.27,2568.87 v1(5666.49,2568.87)
INHC_DRV: C22.1 R76.2 TP22.1 U1.22 | length 1701.2
  Top Layer w10: U1.22@4233.92,2964.09 4233.92,2951.21 4251.63,2933.5 4588.58,2933.5 4603.95,2918.13 5486.76,2918.13 5522.09,2882.81 5522.09,2729.59 5552.09,2699.59 TP22.1@5584.59,2699.59 5584.59,2611.15 C22.1@5583.03,2609.59 R76.2@5583.03,2556.59
INLA: J4.3 R19.1 | length 294.8
  Top Layer w8: R19.1@5028.15,2552.59 5028.15,2486.96 5075.91,2439.2 5075.91,2349.1 J4.3@5029.82,2303
  Bottom Layer w8: J4.3@5029.82,2303 5029.82,2300.39 J4.3@5032.43,2303
INLA_DRV: C19.1 R19.2 TP21.1 U1.19 | length 1129.3
  Top Layer w10: U1.19@4174.87,2964.09 4174.87,2935.13 4227.5,2882.5 4567.46,2882.5 4582.82,2867.13 4901.56,2867.13 4974.59,2794.11 TP21.1@4974.59,2697.59 4974.59,2606.08 C19.1@4973.8,2605.29 4973.8,2553.36 R19.2@4973.03,2552.59
INLB: J4.7 R75.1 | length 367.1
  Top Layer w10: J4.7@5229.82,2303 5243.63,2303 5267.53,2326.91 5269.32,2326.91 5280.33,2337.91 5280.33,2418.24 5324.46,2462.38 5342.92,2462.38 5438.15,2557.6 R75.1@5438.15,2558.59 R75.1@5440.59,2556.15
  Bottom Layer w10: J4.7@5231.12,2301.69 J4.7@5232.43,2303
INLB_DRV: C21.1 R75.2 TP20.1 U1.21 | length 1529.4
  Top Layer w10: U1.21@4214.24,2964.09 4214.24,2945.34 4243.07,2916.5 4581.54,2916.5 4596.91,2901.13 5346.31,2901.13 5386,2861.44 5386,2702 TP20.1@5383.59,2699.59 5383.59,2612.15 C21.1@5383.03,2611.59 R75.2@5383.03,2558.59
INLC: J4.11 R77.1 | length 492
  Top Layer w8: J4.11@5429.82,2303 5474.82,2348 5475,2348 5480,2353 5480,2491.58 5517.27,2528.86 5696.86,2528.86 5719.27,2551.27 5720.25,2551.27 5732,2563.02 R77.1@5732,2564
INLC_DRV: C23.1 R77.2 TP23.1 U1.24 | length 1895.5
  Top Layer w10: U1.24@4254.12,2990.67 4317.66,2990.67 4334.04,2974.28 4571.84,2974.28 4610.99,2935.13 5733.89,2935.13 5785.59,2883.43 TP23.1@5785.59,2702.59 C23.1@5785.59,2618.03 ; C23.1@5785.17,2616.59 5785.17,2565.95 R77.2@5787.12,2564 R77.2@5787.68,2563.44
ISENA: C47.1 J3.14 R70.1 R107.2 TP55.1 | length 678.5
  Top Layer w10: J3.14@5529.82,703 5483.29,749.53 C47.1@5483.29,927 5483.29,984.94 R70.1@5483.82,985.47 5492.29,985.47 5541.82,1035 5541.82,1208.11 5534.82,1215.11 TP55.1@5534.82,1330 ; J3.14@5529.87,703.06 J3.14@5529.93,703
ISENB: C48.1 J3.16 R71.1 R108.2 TP56.1 | length 676.5
  Top Layer w8: J3.16@5629.82,703 5659.35,732.53 5659.35,988.94 R71.1@5656.82,991.47 5651.1,991.47 5618.26,1024.32 5618.26,1094.14 5663.82,1139.7 TP56.1@5663.82,1328
ISENC: C49.1 J3.18 R72.1 R109.2 TP57.1 | length 660.5
  Top Layer w8: J3.18@5729.82,703 5729.82,838.47 R109.2@5716.29,852 5716.29,924 C49.1@5715.29,925 5715.29,974.94 R72.1@5730.82,990.47 5736.53,990.47 5792.82,1046.76 TP57.1@5792.82,1322
K_OUTA: NT9.2 TP4.1 TP5.1 | length 1294.6
  Top Layer w10: TP5.1@3364.77,4340.4 3353.42,4329.05 3353.42,4224.53 TP4.1@3342.08,4213.18 3329,4200.1 3329,3573 3605,3297 3685,3297 3690,3292 NT9.2@3725,3292
K_OUTB: NT10.2 TP6.1 TP7.1 | length 924
  Top Layer w10: TP7.1@3811.2,4254.2 3774,4217 3774,3703.34 3882.34,3595 3900,3595 NT10.2@3900,3573 ; TP7.1@3816.29,4245.27 3905.54,4334.52 TP6.1@3905.54,4348.54 ; TP6.1@3892.63,4346.56 TP6.1@3910.07,4364
K_OUTC: NT11.2 TP9.1 TP10.1 | length 776.3
  Top Layer w10: NT11.2@4349,3284 v1(4388,3284)
  Bottom Layer w8: v1(4388,3284) 4514.9,3284 4605.9,3375 4624.41,3375 4656.93,3342.48 4695,3342.48 4820.52,3468 TP10.1@4821.5,3468 4830.24,3476.74 4830.24,3652.68 TP9.1@4838.99,3661.43
MCU_LED: J4.20 R17.1 | length 129.6
  Top Layer w10: J4.20@5820.06,2412.76 J4.20@5829.82,2403 5829.82,2412.62 5857.19,2439.99 R17.1@5857.19,2507.47
NetC1_2: C1.2 C59.1 D14.1 TP29.1 U1.48 | length 1252.7
  Top Layer w10: TP29.1@3684,4449 3621,4386 3621,3881 3621,3869.06 C59.1@3621,3603 3621,3577.15 C1.2@3694,3504.15 3790.85,3504.15 3805.61,3489.39 3861.82,3489.39 3902.58,3448.63 U1.48@3902.58,3428.66
NetC2_1: C2.1 L1.1 U4.2 | length 120.4
  Top Layer w10: U4.2@2218.7,806.82 2218.7,794.74 2240.27,773.17 2317.73,773.17 C2.1@2318,773.44
NetC2_2: C2.2 U4.6 | length 85.8
  Top Layer w10: U4.6@2256.11,700.52 2256.11,717.55 2272.63,734.07 C2.2@2318,734.07
NetC3_2: C3.2 C60.1 D16.1 TP32.1 U1.43 | length 984.9
  Top Layer w10: U1.43@4056.76,3428.66 4056.76,3441.76 4130.5,3515.5 4130.5,3566 4130.5,3618.15 4176.76,3664.41 4176.76,3693 4176.76,3837.76 4177,3838 4232,3893 4232,3964 TP32.1@4232,4341
NetC4_1: C4.1 J8.1 R14.2 | length 225.3
  Top Layer w10: J8.1@4095.7,1168 4132.7,1131 C4.1@4226.47,1131 4226.47,1189 R14.2@4211.47,1204
NetC5_2: C5.2 C61.1 D15.1 TP34.1 U1.41 | length 1089.8
  Top Layer w10: U1.41@4170.93,3428.66 4170.93,3449.52 4250.56,3529.15 4369,3529.15 4385.66,3545.8 4385.66,3557.81 4404,3576.15 4404,3578.43 C61.1@4425.57,3600 4419.15,3606.43 4419.15,3867 4419.15,4177 4419.15,4324.15 4431,4336
NetC7_1: C7.1 C29.1 C30.1 C31.1 J17.2 TP33.1 U4.3 U4.5 | length 400.6
  Top Layer w15: U4.3@2181.3,806.82 2181.3,773.86 2218.7,736.46 U4.5@2218.7,700.52
  Bottom Layer w30: TP33.1@1920,1213 2065.83,1213 2152.39,1126.44 J17.2@2163,1126.44
NetC11_1: C11.1 C12.2 R9.2 R10.1 | length 864.4
  Top Layer w8: C12.2@4374,2724.44 4376.37,2722.07 R9.2@4376.37,2681 ; C12.2@4374,2727.44 4415.24,2727.44 4420.9,2721.78 4420.9,2721 4431.61,2710.29 v1(4431.61,2707.04)
  Top Layer w10: R10.1@3823,2811.32 3823,2775.69 C11.1@3823.68,2775 3844.82,2753.87 v1(3845,2753.87)
  Ground w8: v1@3847.13,2753.87 v1(3845,2753.87) 3885.33,2713.54 3989.89,2713.54 3991.35,2715 4037.92,2715 4072.84,2680.08 4242.77,2680.08 4251.77,2671.08 v1(4250.5,2669.81)
  Power w8: v1(4250.5,2669.81) 4250.5,2673.05 4256.5,2679.05 4256.5,2705.89 4284.61,2734 4408.48,2734 4429.31,2713.17 4429.31,2712.59 4431.61,2710.29 v1(4431.61,2707.04)
NetC11_2: C11.2 C36.1 R11.2 R12.1 | length 888.5
  Top Layer w8: R11.2@4378.69,2642 4378.69,2603.84 C36.1@4385,2597.53 ; R11.2@4380.65,2642 4408.07,2669.42 4408.07,2690.72 v1(4408.78,2691.42)
  Top Layer w10: R12.1@3784,2812.32 3784.31,2812 C11.2@3784.31,2775 3807,2752.31 v1(3807,2748)
  Ground w8: v1(3807,2748) 3816,2748 3817,2749 3867.92,2698.08 4032.98,2698.08 4066.44,2664.62 4218.24,2664.62 4234.52,2648.35 v1@4259.39,2648.35
  Power w8: v1(4268,2652) 4268,2655.25 4271.96,2659.2 4271.96,2699.48 4291.01,2718.54 4393.59,2718.54 4404.99,2707.14 4404.99,2698.45 4408.78,2694.67 v1(4408.78,2691.42)
NetC17_1: C17.1 R46.1 R53.2 U5.2 | length 423.4
  Top Layer w10: U5.2@4034.12,1413.33 4038.85,1418.06 4006.77,1418.06 3994.56,1430.28 3994.56,1447.56 4013,1466 4015.47,1466 C17.1@4104.47,1555 4104.47,1580.36 4160.83,1636.71 4160.83,1656.69 4171.57,1667.44 R53.2@4172.56,1667.44 4173.68,1668.56 R46.1@4226.56,1668.56
NetC24_1: C24.1 R58.1 R60.2 U5.6 | length 612
  Top Layer w10: C24.1@3749,1670.53 3810.43,1670.53 R58.1@3814.26,1666.7 3815.14,1667.59 R60.2@3867.26,1667.59 3867.26,1364.99 3921.29,1310.96 U5.6@4034.12,1310.96
NetC28_1: C28.1 C33.1 R54.1 U2.5
NetC37_2: C37.2 C39.1 R52.2 R53.1 | length 162.2
  Top Layer w10: R52.2@4169.56,1818.44 4169.56,1770.56 C39.1@4170.12,1770 ; R53.1@4172.56,1722.56 4170.12,1725 C39.1@4170.12,1770 ; C37.2@4234,1767 4173.12,1767 C39.1@4170.12,1770
NetC38_2: C38.2 R47.1 U5.4 | length 205.9
  Top Layer w15: R47.1@3953.26,1504.59 3953.26,1394.62 3979.94,1367.93 C38.2@3979.94,1365.14 3982.94,1362.14 U5.4@4034.12,1362.14
NetC39_2: C39.2 C40.1 R55.2 R56.1 | length 169.3
  Top Layer w10: C40.1@4048.26,1761.68 4106.68,1761.68 C39.2@4115,1770 ; R56.1@4113.56,1722.56 4115,1724 C39.2@4115,1770 ; R55.2@4113.56,1820.44 4113.56,1771.44 C39.2@4115,1770
NetC41_2: C41.2 C42.1 R59.2 R60.1 | length 164.5
  Top Layer w10: C41.2@3800,1768.47 3864.03,1768.47 C42.1@3866.7,1771.14 ; R59.2@3865.26,1818.59 3865.26,1772.59 C42.1@3866.7,1771.14 ; R60.1@3867.26,1722.7 3867.26,1770.59 C42.1@3866.7,1771.14
NetC42_2: C42.2 C43.1 R61.2 R62.1 | length 162.7
  Top Layer w10: R62.1@3920.26,1722.7 3921.82,1724.26 C42.2@3921.82,1771.14 ; R61.2@3920.26,1818.59 3921.82,1817.03 C42.2@3921.82,1771.14 ; C43.1@3985,1768.47 3985,1770.59 3922.37,1770.59 C42.2@3921.82,1771.14
NetC44_2: C44.2 C45.1 R65.2 R66.1 | length 181.6
  Top Layer w10: R66.1@4402.56,1726.56 4404.12,1728.12 C45.1@4404.12,1775 ; R65.2@4414,1826.44 4414,1784.88 C45.1@4404.12,1775 ; C44.2@4479,1770 4474,1775 C45.1@4404.12,1775
NetC45_2: C45.2 C46.1 R67.2 R68.1 | length 159.7
  Top Layer w10: C46.1@4296,1770 4344,1770 C45.2@4349,1775 ; R68.1@4348.56,1726.56 4349,1727 C45.2@4349,1775 ; R67.2@4361,1826 4361,1787.98 4349,1775.98 C45.2@4349,1775
NetC50_1: C50.1 R64.1 R66.2 U5.9 | length 557.3
  Top Layer w8: R66.2@4403.44,1670.56 R64.1@4455.56,1670.56
  Top Layer w10: U5.9@4266.4,1310.96 4303.15,1310.96 4378.26,1386.07 4378.26,1645.37 4390.83,1657.94 4390.83,1660.69 4400.69,1670.56 R66.2@4403.44,1670.56 ; R64.1@4455.56,1670.56 4457.91,1672.91 C50.1@4520.3,1672.91
NetC52_2: C52.2 R8.1 R45.2 R129.2 | length 836.7
  Top Layer w8: R45.2@3862,2811.31 3862,2784 v1(3863,2783) ; v1(4257,2566) 4267.32,2566 R8.1@4288,2545.32 4326,2545.32 R129.2@4327,2544.31 4327,2487.56 C52.2@4326.44,2487
  Ground w8: v1(3863,2783) 3811.65,2783 3785.54,2756.89 3785.54,2739.11 3842.03,2682.62 4026.58,2682.62 4060.04,2649.16 4211.84,2649.16 4257,2604 v1(4257,2566)
NetC56_1: C56.1 D7.2 F1.1 R121.2 RV1.2 | length 248.4
  Top Layer w20: C56.1@1459.72,4339.36 1465.82,4333.26 1465.82,4102.09 R121.2@1471.91,4096
  other v1: 1391.77,4403.7 1541.77,4403.7 1473,4476 1616,4509 1391.77,4553.7 1541.77,4553.7 1491,4620 1639,4662 1541.77,4703.7 1636,4968 1541.77,5003.7 1504,5079 1182,5097 1306,5101 1241.77,5153.7 1391.77,5153.7 1541.77,5153.7 1155,5183 1318,5199 1473,5199 1241.77,5258.77 1391.77,5258.77
NetC56_2: C56.2 D7.3 J19.2 R122.1 RV1.1 | length 260.4
  Top Layer w20: R122.1@2011.5,4095 2011.5,4293.95 2050.28,4332.72 C56.2@2050.28,4339.36
  other v1: 1994,4393 2034,4476 1934,4489.55 1834,4589.55 1934,4589.55 1834,4689.55 1834,4989.55 1916,5063 1834,5189.55 1916,5238 1834,5289.55 1910,5333 1834,5389.55 1834,5489.55
NetD2_2: D2.2 R15.2 | length 85.1
  Top Layer w10: R15.2@4695,2993.86 4779.78,2993.86 D2.2@4780,2994.08
NetD3_2: D3.2 R16.2 | length 65.5
  Top Layer w20: R16.2@1394.56,1561.34 1456.34,1561.34 D3.2@1459,1564
NetD4_2: D4.2 R17.2 | length 132.1
  Top Layer w10: R17.2@5848.99,2555.69 R17.2@5856.54,2563.24 ; R17.2@5857.19,2562.59 5977.45,2562.59 D4.2@5978.28,2561.76
NetD7_1: D7.1 RT1.1
  other v1: 1089,4578 927,4595 1035,4646 1210,4646 958,4688 903,4768 1207,4768 1035,4770 1350,4782 973,4859.82 1123,4859.82 1273,4859.82
NetF1_2: F1.2 J19.3
  other v1: 1155,5466 1273,5466 1391.77,5466 1155,5551 1273,5551 1356,5560
NetF2_1: F2.1 RT1.2
  other v1: 838,4023 1013,4023 941.77,4103.7 1091.77,4103.7 1204,4154 852,4164 1013,4182 823,4247 941.77,4253.7 1091.77,4253.7
NetJ1_5: J1.5 R43.2 | length 110.2
  Top Layer w10: R43.2@2913.23,1677.44 2913.79,1678 J1.5@3023.23,1678
NetJ1_7: J1.7 R44.2 | length 109.6
  Top Layer w10: R44.2@2914.23,1579.47 2915.7,1578 J1.7@3023.23,1578
NetJ2_1: J2.1 TP52.1 | length 181.1
  Top Layer w20: J2.1@5897,5404 5899,5406 TP52.1@6069,5406 TP52.1@6074.87,5411.87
